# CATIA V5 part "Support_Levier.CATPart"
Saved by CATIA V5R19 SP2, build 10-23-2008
Part number: Support_Levier
Bounding box of the stored display mesh (mm): x 0 to 1, y -8 to 79, z -11.479 to 7.373
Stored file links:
  G:\EU_thinkMotion\CFAO_2010\MMS_groupe3\MMS_groupe3\A reprendre\lletoffe\lletoffe_Thinkmotion_CFAO\Modèle Catia\Support_Levier.CATPart
  E:\CFAO\Last Catia\support levier.CATPart
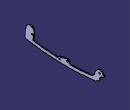
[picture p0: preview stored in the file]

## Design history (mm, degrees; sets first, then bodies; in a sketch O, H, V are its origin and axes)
Parameters
  Epaisseur = 1 mm
Set1
  Point1: (0, 30.2, -8.3)
  Point2: (1, 30.2, -8.3)
  Line1: type PtPt, FirstPoint Point1, SecondPoint Point2, Start 10, End 10
  Point3: (1, 38.5, -6.2)
  Point4: (0, 38.5, -6.2)
  Line2: type PtPt, FirstPoint Point3, SecondPoint Point4, Start 10, End 10
  Point5: (0, 0, 0)
  Point6: (1, 0, 0)
  Line3: type PtPt, FirstPoint Point5, SecondPoint Point6, Start 10, End 10
  Point7: (1, 74, 0)
  Point8: (0, 74, 0)
  Line4: type PtPt, FirstPoint Point7, SecondPoint Point8, Start 10, End 10
  Plane1: type Offset, RefPlane yz-plane, Offset 1 {= Epaisseur}
  Sketch1 on yz-plane, origin (0, 0, 0), H (0, 1, 0), V (0, 0, 1)
    circle A1 centre (0, 0) radius 1
    arc A2 centre (36.9998, -5.8768) radius 45 from (-6.9159, 3.9421) to (-8, -6.005) ccw
    arc A3 centre (-6.25, -6) radius 1.75 from (-8, -6.005) to (-6.5549, -7.7232) ccw
    point P1 (-6.25, -6)
    circle A4 centre (38.5, -6.2) radius 1
    circle A5 centre (30.2, -8.3) radius 1
    arc A6 centre (1.715, -4.6707) radius 1 from (0.7302, -4.497) to (1.5733, -5.6606) ccw
    line L1 (1.9073, 2.1788) -> (0.7302, -4.497)
    arc A7 centre (30.2, -8.3) radius 2 from (29.7094, -6.3611) to (28.3969, -7.4346) ccw
    arc A8 centre (38.5, -6.2) radius 2 from (40.4846, -6.4478) to (38.0094, -4.2611) ccw
    line L2 (29.7094, -6.3611) -> (38.0094, -4.2611)
    construction line L3 through (-0.0149, 0) direction (1, 0)
    construction line L4 through (0, -0.6626) direction (0, 1)
    arc A9 centre (41.973, -6.6337) radius 1.5 from (40.4846, -6.4478) to (42.003, -8.1334) ccw
    arc A10 centre (27.4954, -7.002) radius 1 from (27.4572, -8.0012) to (28.3969, -7.4346) ccw
    line L5 (69.5, 0) -> (70.0314, 0)
    point P7 (74, 0)
    arc A11 centre (77.9686, 0.5) radius 0.5 from (77.4725, 0.4375) to (77.9686, 0) ccw
    arc A12 centre (70.0314, 0.5) radius 0.5 from (70.0314, 0) to (70.5275, 0.4375) ccw
    point P8 (77.9686, 0)
    arc A13 centre (69.5, -0.5) radius 0.5 from (69.5, 0) to (69, -0.5) ccw
    arc A14 centre (78.5, -0.5) radius 0.5 from (79, -0.5) to (78.5, 0) ccw
    line L6 (79, -0.5) -> (79, -1.5)
    point P9 (79, -0.5)
    point P10 (79, -0.5)
    line L7 (69, -1.5) -> (69, -0.5)
    point P11 (69, -0.5)
    point P12 (69, -0.5)
    arc A15 centre (63.7866, -1.5) radius 5.2134 from (64.3571, -6.6821) to (69, -1.5) ccw
    line L8 (69.4199, -9.3581) -> (73.75, -6.8581)
    arc A16 centre (68.9199, -8.4921) radius 1 from (69.0481, -9.4839) to (69.4199, -9.3581) ccw
    arc A17 centre (77.4495, -5.4495) radius 3.4495 from (77.4495, -2) to (74, -5.4495) ccw
    line L9 (74, -5.4495) -> (74, -6.4251)
    arc A18 centre (73.5, -6.4251) radius 0.5 from (73.75, -6.8581) to (74, -6.4251) ccw
    point P13 (73.75, -6.8581)
    point P14 (73.75, -6.8581)
    line L10 (77.4495, -2) -> (78.5, -2)
    arc A19 centre (78.5, -1.5) radius 0.5 from (78.5, -2) to (79, -1.5) ccw
    point P15 (78.5, -2)
    point P16 (78.5, -2)
    line L11 (77.9686, 0) -> (78.5, 0)
    point P17 (78.5, 0)
    point P18 (69.5, 0)
    point P19 (-6.5549, -7.7232)
    arc A20 centre (37, 238.4535) radius 250 from (-6.5549, -7.7232) to (69.0481, -9.4839) ccw
    point P20 (-6.5549, -7.7232)
    axis line L12 (37, 241.8166) -> (37, 238.4535)
    arc A21 centre (37, 241.8166) radius 250 from (42.003, -8.1334) to (64.3571, -6.6821) ccw
    arc A22 centre (37, 241.8166) radius 250 from (1.5733, -5.6606) to (27.4572, -8.0012) ccw
    arc A23 centre (74, 0) radius 3.5 from (77.4725, 0.4375) to (70.5275, 0.4375) ccw
    arc A24 centre (-2.5243, 2.9602) radius 4.5 from (1.9073, 2.1788) to (-6.9159, 3.9421) ccw
    point P21 (36.9998, -5.8768)
    point P22 (74, 0)
    circle A25 centre (74, 0) radius 1
    point P23 (0, 0)
    point P24 (1.715, -4.6707)
    reference projected point E1 (0, 0) from Line3
    reference projected point E2 (30.2, -8.3) from Line1
    reference projected point E3 (38.5, -6.2) from Line2
    reference projected point E4 (74, 0) from Line4
    radius A1 = 1
    radius A3 = 1.75
    radius A4 = 1
    radius A5 = 1
    radius A6 = 1
    distance A7 A5 = 1
    distance A4 A8 = 1
    radius A9 = 1.5
    radius A10 = 1
    radius A12 = 0.5
    radius A11 = 0.5
    distance A14 A13 = 10
    radius A14 = 0.5
    radius A13 = 0.5
    length L7 = 1
    angle L8 L5 = 30
    radius A16 = 1
    radius A19 = 0.5
    radius A18 = 0.5
    distance A17 P7 = 3
    distance L9 L7 = 5
    distance L10 L5 = 2
    length L8 = 5
    radius A20 = 250
    radius A21 = 250
    distance L4 P1 = 6.25
    radius A2 = 45
    distance P21 L4 = 36.9998
    radius A22 = 250
    radius A23 = 3.5
    radius A25 = 1
    distance L1 P23 = 1.5
    angle L1 L4 = 10
    distance L12 L4 = 37
    distance L3 P1 = 6
    distance P24 L4 = 1.715
    radius A24 = 4.5
    tangency: A3 A2, L1 A6, L2 A8, L2 A7, A10 A7, A9 A8, A11 L5, A12 L5, A13 L5, A14 L5, L6 A14, A13 L7, A15 L7, A16 L8, L9 A17, A18 L9, A18 L8, L10 A17, A19 L6, A19 L10, A3 A20, A22 A10, A9 A21, A21 A15, A12 A23, A11 A23, A16 A20, A24 L1, A2 A24, A6 A22
    horizontal: L5 L3, L10 L3, L11 L3
    coincidence: L5 P7, P8 L5, P10 P9, P12 P11, P14 P13, P16 P15, L5 L11, A3 P19, P19 P20, P22 L3, P23 L3, P23 L4
    vertical: L6 L4, L7 L4, L9 L4
    equidistance: P18 P17 P7
    concentricity: P22 A23, A23 A25, E1 A1, E2 A5, E3 A4, A25 E4
    perpendicularity: L3 L4
Body1 (main body)
  Pad1: profile Sketch1, direction (1, 0, 0), up to Plane1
